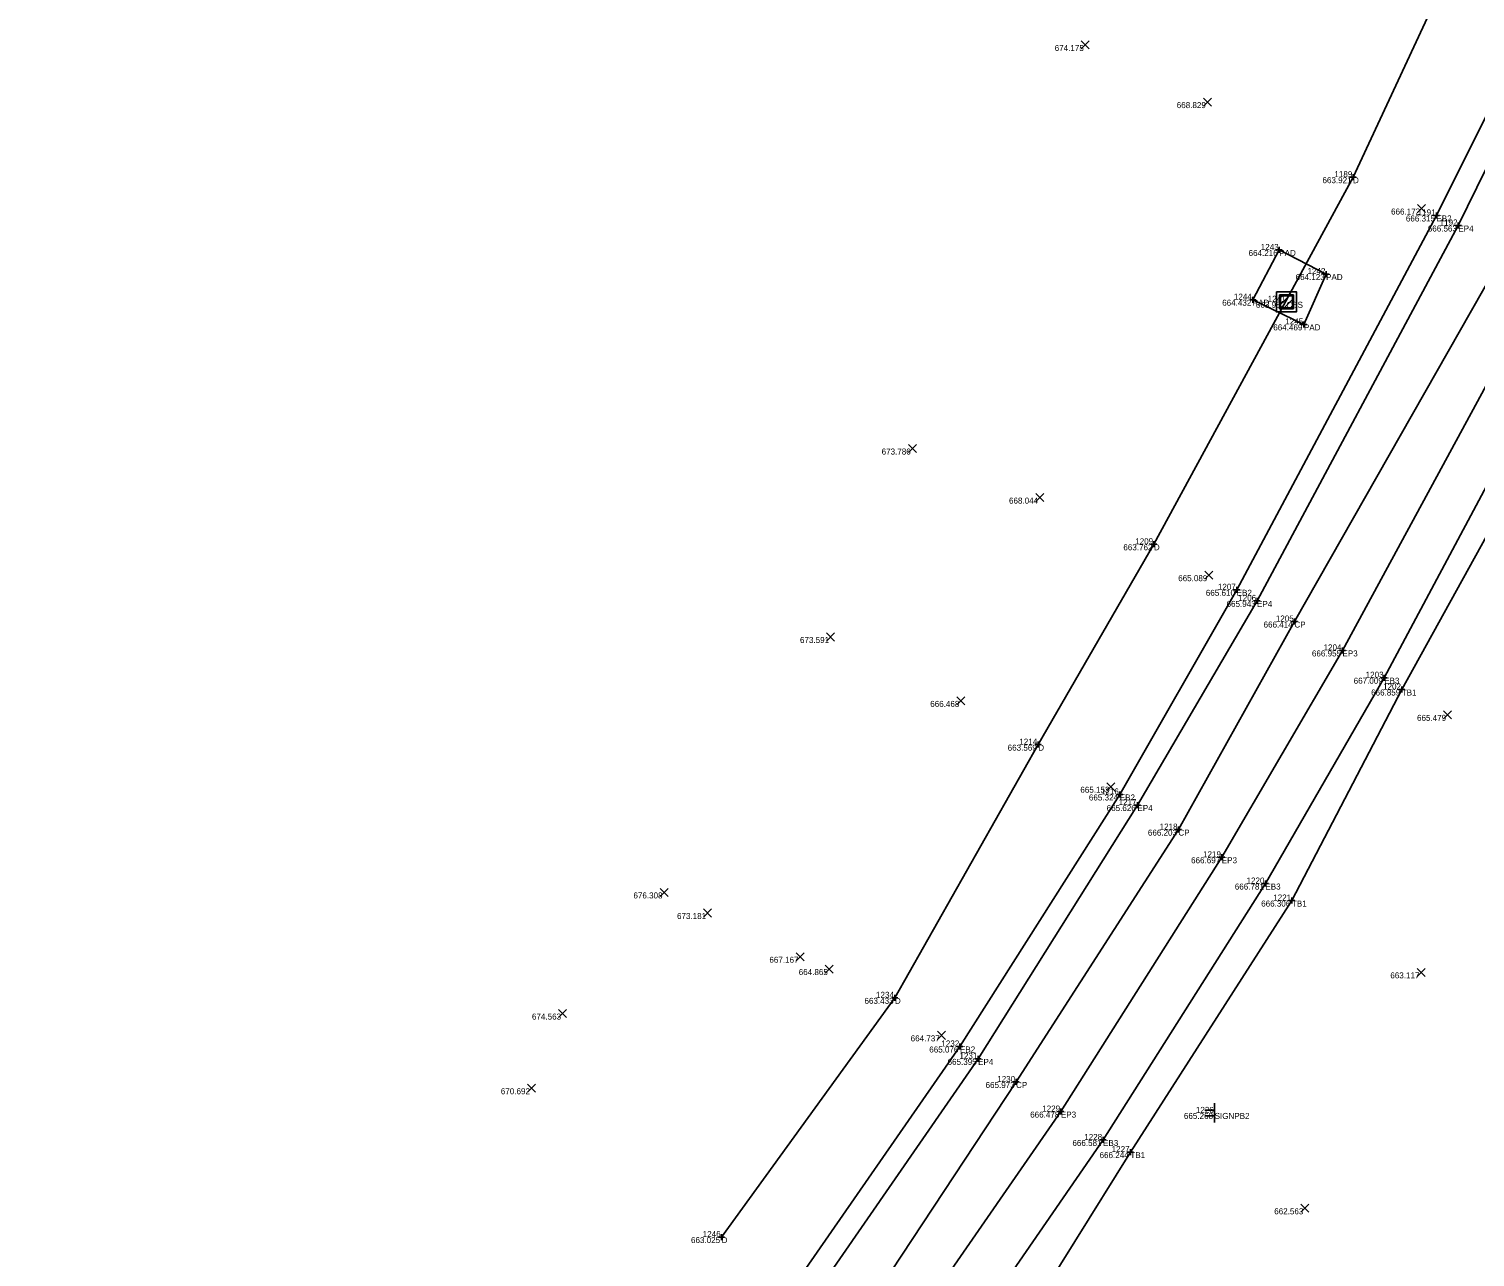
# Model space of a CAD drawing. Extents: x 2197382 to 2204062, y 634117 to 636522.
# Drawn here: x 2202848 to 2203088.2, y 635670.7 to 635874.6 of the extents above; entities that cross this region are included whole.
import ezdxf

# ---------------------------------------------------------------- set-up
doc = ezdxf.new("R2010")
doc.units = 0
for name, color, linetype in [('_CIVIL_CONSTRUCTION', 7, 'Continuous'), ('BR_P_Gen_Approach_Slab', 7, 'Continuous'), ('DR_X_Ditch', 7, 'Continuous'), ('GE_P_Alignment', 7, 'Continuous'), ('GE_P_Alignment_100_Cardinal_Points', 7, 'Continuous'), ('GE_P_Alignment_100_Distances', 7, 'Continuous'), ('GE_P_Alignment_100_Stations', 7, 'Continuous'), ('GE_X_Alignment', 7, 'Continuous'), ('PF_P_Grade_Line', 7, 'Continuous'), ('PV_X_COP', 7, 'Continuous'), ('RW_X_CL_100_Curve_Data', 7, 'Continuous'), ('SH_Border', 7, 'Continuous'), ('SH_Cut_Line', 7, 'Continuous'), ('SH_Data', 7, 'Continuous')]:
    doc.layers.add(name, color=color, linetype=linetype)

msp = doc.modelspace()

# ---------------------------------------------------------------- linework, layer by layer
at = {"layer": '_CIVIL_CONSTRUCTION'}
for p, q in [((2203067.39, 635850.01), (2203068.39, 635850.01)), ((2203067.89, 635850.51), (2203067.89, 635849.51)), ((2203067.89, 635850.01), (2203067.89, 635850.01)), ((2203081.23, 635843.65), (2203082.23, 635843.65)), ((2203081.73, 635844.15), (2203081.73, 635843.15)), ((2203081.73, 635843.65), (2203081.73, 635843.65)), ((2203084.87, 635841.98), (2203085.87, 635841.98)), ((2203085.37, 635842.48), (2203085.37, 635841.48)), ((2203085.37, 635841.98), (2203085.37, 635841.98)), ((2203055.14, 635837.92), (2203056.14, 635837.92)), ((2203055.64, 635838.42), (2203055.64, 635837.42)), ((2203055.64, 635837.92), (2203055.64, 635837.92)), ((2203062.91, 635833.92), (2203063.91, 635833.92)), ((2203063.41, 635834.42), (2203063.41, 635833.42)), ((2203063.41, 635833.92), (2203063.41, 635833.92)), ((2203050.73, 635829.66), (2203051.73, 635829.66)), ((2203051.23, 635830.16), (2203051.23, 635829.16)), ((2203051.23, 635829.66), (2203051.23, 635829.66)), ((2203059.73, 635826.06), (2203059.73, 635825.06)), ((2203059.23, 635825.56), (2203060.23, 635825.56)), ((2203059.73, 635825.56), (2203059.73, 635825.56)), ((2203034.31, 635789.04), (2203035.31, 635789.04)), ((2203034.81, 635789.54), (2203034.81, 635788.54)), ((2203034.81, 635789.04), (2203034.81, 635789.04)), ((2203048.06, 635781.48), (2203049.06, 635781.48)), ((2203048.56, 635781.98), (2203048.56, 635780.98)), ((2203048.56, 635781.48), (2203048.56, 635781.48)), ((2203051.94, 635780.14), (2203051.94, 635779.14)), ((2203051.44, 635779.64), (2203052.44, 635779.64)), ((2203051.94, 635779.64), (2203051.94, 635779.64)), ((2203057.65, 635776.21), (2203058.65, 635776.21)), ((2203058.15, 635776.71), (2203058.15, 635775.71)), ((2203058.15, 635776.21), (2203058.15, 635776.21)), ((2203065.63, 635771.41), (2203066.63, 635771.41)), ((2203066.13, 635771.91), (2203066.13, 635770.91)), ((2203066.13, 635771.41), (2203066.13, 635771.41)), ((2203072.57, 635766.88), (2203073.57, 635766.88)), ((2203073.07, 635767.38), (2203073.07, 635766.38)), ((2203073.07, 635766.88), (2203073.07, 635766.88)), ((2203075.48, 635764.92), (2203076.48, 635764.92)), ((2203075.98, 635765.42), (2203075.98, 635764.42)), ((2203075.98, 635764.92), (2203075.98, 635764.92)), ((2203015.61, 635756.26), (2203015.61, 635755.26)), ((2203015.11, 635755.76), (2203016.11, 635755.76)), ((2203015.61, 635755.76), (2203015.61, 635755.76)), ((2203028.65, 635747.49), (2203029.65, 635747.49)), ((2203029.15, 635747.99), (2203029.15, 635746.99)), ((2203029.15, 635747.49), (2203029.15, 635747.49)), ((2203031.58, 635745.73), (2203032.58, 635745.73)), ((2203032.08, 635746.23), (2203032.08, 635745.23)), ((2203032.08, 635745.73), (2203032.08, 635745.73)), ((2203038.88, 635742.15), (2203038.88, 635741.15)), ((2203038.38, 635741.65), (2203039.38, 635741.65)), ((2203038.88, 635741.65), (2203038.88, 635741.65)), ((2203045.59, 635737.06), (2203046.59, 635737.06)), ((2203046.09, 635737.56), (2203046.09, 635736.56)), ((2203046.09, 635737.06), (2203046.09, 635737.06)), ((2203052.83, 635732.69), (2203053.83, 635732.69)), ((2203053.33, 635733.19), (2203053.33, 635732.19)), ((2203053.33, 635732.69), (2203053.33, 635732.69)), ((2203057.24, 635729.87), (2203058.24, 635729.87)), ((2203057.74, 635730.37), (2203057.74, 635729.37)), ((2203057.74, 635729.87), (2203057.74, 635729.87)), ((2202991.31, 635713.71), (2202992.31, 635713.71)), ((2202991.81, 635714.21), (2202991.81, 635713.21)), ((2202991.81, 635713.71), (2202991.81, 635713.71)), ((2203002.11, 635705.63), (2203003.11, 635705.63)), ((2203002.61, 635706.13), (2203002.61, 635705.13)), ((2203002.61, 635705.63), (2203002.61, 635705.63)), ((2203005.12, 635703.58), (2203006.12, 635703.58)), ((2203005.62, 635704.08), (2203005.62, 635703.08)), ((2203005.62, 635703.58), (2203005.62, 635703.58)), ((2203011.42, 635699.74), (2203012.42, 635699.74)), ((2203011.92, 635700.24), (2203011.92, 635699.24)), ((2203011.92, 635699.74), (2203011.92, 635699.74)), ((2203018.87, 635694.82), (2203019.87, 635694.82)), ((2203019.37, 635695.32), (2203019.37, 635694.32)), ((2203019.37, 635694.82), (2203019.37, 635694.82)), ((2203025.87, 635690.11), (2203026.87, 635690.11)), ((2203026.37, 635690.61), (2203026.37, 635689.61)), ((2203026.37, 635690.11), (2203026.37, 635690.11)), ((2203030.41, 635688.09), (2203031.41, 635688.09)), ((2203030.91, 635688.59), (2203030.91, 635687.59)), ((2203030.91, 635688.09), (2203030.91, 635688.09)), ((2202963.02, 635674.48), (2202963.02, 635673.48)), ((2202962.52, 635673.98), (2202963.52, 635673.98)), ((2202963.02, 635673.98), (2202963.02, 635673.98))]:
    msp.add_line(p, q, dxfattribs=at)
at = {"layer": 'BR_P_Gen_Approach_Slab'}
msp.add_lwpolyline([(2203063.41, 635833.92), (2203055.64, 635837.92), (2203051.23, 635829.66), (2203059.73, 635825.56)], close=True, dxfattribs=at)
at = {"layer": 'DR_X_Ditch'}
msp.add_lwpolyline([(2203184.1, 636112.24), (2203164.63, 636065.3), (2203144.25, 636021.99), (2203126.27, 635973.65), (2203105.52, 635930.12), (2203083.98, 635884.54), (2203067.89, 635850.01), (2203034.81, 635789.04), (2203015.61, 635755.76), (2202991.81, 635713.71), (2202963.02, 635673.98)], dxfattribs=at)
at = {"layer": 'GE_P_Alignment'}
for p, q in [((2203055.68, 635828.69), (2203057.44, 635830.45)), ((2203055.68, 635829.83), (2203056.3, 635830.45)), ((2203056.28, 635828.16), (2203057.97, 635829.85)), ((2203057.41, 635828.16), (2203057.97, 635828.72))]:
    msp.add_line(p, q, dxfattribs=at)
for points in [[(2203055.16, 635830.97), (2203058.49, 635830.97), (2203058.49, 635827.64), (2203055.16, 635827.64)], [(2203055.68, 635830.45), (2203057.97, 635830.45), (2203057.97, 635828.16), (2203055.68, 635828.16)], [(2203055.82, 635830.31), (2203057.82, 635830.31), (2203057.82, 635828.31), (2203055.82, 635828.31)]]:
    msp.add_lwpolyline(points, close=True, dxfattribs=at)
at = {"layer": 'GE_P_Alignment_100_Cardinal_Points'}
for p, q in [((2203056.82, 635830.97), (2203056.82, 635830.97)), ((2203055.82, 635829.31), (2203055.82, 635829.31)), ((2203056.82, 635830.31), (2203056.82, 635830.31)), ((2203056.82, 635829.31), (2203056.82, 635829.31)), ((2203056.82, 635829.31), (2203056.82, 635829.31)), ((2203056.82, 635829.31), (2203056.82, 635829.31)), ((2203056.82, 635828.31), (2203056.82, 635828.31)), ((2203057.82, 635829.31), (2203057.82, 635829.31)), ((2203056.82, 635827.64), (2203056.82, 635827.64))]:
    msp.add_line(p, q, dxfattribs=at)
at = {"layer": 'GE_P_Alignment_100_Distances'}
for points in [[(2203324.48, 636507.85), (2203318.62, 636484.14), (2203306.91, 636435.63), (2203294.22, 636387.53), (2203281.02, 636340.01), (2203266.86, 636291.74), (2203251.88, 636244.73), (2203235.99, 636197.91), (2203219.31, 636150.6), (2203201.96, 636104.73), (2203183.73, 636058.36), (2203164.29, 636012.58), (2203144.31, 635966.64), (2203123.63, 635921.48), (2203102.28, 635876.46), (2203085.37, 635841.98), (2203051.94, 635779.64), (2203032.08, 635745.73), (2203005.62, 635703.58), (2202977.57, 635663.01), (2202948.44, 635623.54), (2202917.31, 635585.47), (2202885.13, 635547.53), (2202851.31, 635511.58)], [(2203340.49, 636502.89), (2203334.83, 636480.1), (2203323.13, 636431.59), (2203310.29, 636383.13), (2203297.23, 636335.04), (2203282.66, 636287.13), (2203267.38, 636239.56), (2203251.38, 636192.17), (2203234.81, 636145.08), (2203217.29, 636098.29), (2203199.14, 636051.74), (2203179.44, 636005.69), (2203159.56, 635959.77), (2203137.84, 635914.65), (2203117.45, 635869.06), (2203100.66, 635835.13), (2203066.13, 635771.41), (2203046.09, 635737.06), (2203019.37, 635694.82), (2202991.01, 635653.88), (2202961.19, 635613.48), (2202929.73, 635574.61), (2202897.41, 635536.46), (2202863.17, 635499.96)]]:
    msp.add_lwpolyline(points, dxfattribs=at)
at = {"layer": 'GE_P_Alignment_100_Stations'}
for p, q in [((2203044.9, 635696.2), (2203044.9, 635693)), ((2203044.9, 635695.08), (2203043.3, 635695.08)), ((2203044.9, 635694.12), (2203043.3, 635694.12)), ((2203044.9, 635694.6), (2203044.9, 635694.6))]:
    msp.add_line(p, q, dxfattribs=at)
at = {"layer": 'GE_X_Alignment'}
for points in [[(2203321.2, 636508.87), (2203315.42, 636484.99), (2203303.56, 636436.4), (2203290.91, 636388.48), (2203277.67, 636341.19), (2203263.29, 636292.83), (2203248.5, 636245.95), (2203232.65, 636199.01), (2203215.82, 636151.66), (2203198.58, 636105.93), (2203180.2, 636059.59), (2203161.3, 636014.11), (2203141.29, 635968.09), (2203120.26, 635923.09), (2203098.92, 635878.1), (2203081.73, 635843.65), (2203048.56, 635781.48), (2203029.15, 635747.49), (2203002.61, 635705.63), (2202974.64, 635665.31), (2202945.56, 635625.56), (2202914.38, 635588.2), (2202882.41, 635550.01), (2202847.99, 635514.11)], [(2203331.27, 636429.38), (2203318.29, 636380.99), (2203304.79, 636332.88), (2203290.18, 636284.77), (2203275.23, 636236.57), (2203259.29, 636189.41), (2203242.5, 636142.16), (2203224.73, 636095.35), (2203206.44, 636048.57), (2203187.1, 636002.46), (2203167.05, 635956.43), (2203145.71, 635910.9), (2203124.58, 635865.62), (2203107.54, 635831.47), (2203073.07, 635766.88), (2203053.33, 635732.69), (2203026.37, 635690.11), (2202997.51, 635648.24), (2202967.93, 635608.32), (2202935.99, 635569.18), (2202902.86, 635531.15), (2202868.61, 635494.33)]]:
    msp.add_lwpolyline(points, dxfattribs=at)
at = {"layer": 'PF_P_Grade_Line'}
msp.add_lwpolyline([(2203263.6, 636187.64), (2203248.97, 636139.91), (2203228.73, 636093.53), (2203209.69, 636047.17), (2203190.81, 636000.71), (2203171.68, 635954.63), (2203151.19, 635908.23), (2203127.58, 635864.5), (2203111.43, 635829.11), (2203075.98, 635764.92), (2203057.74, 635729.87), (2203030.91, 635688.09), (2203003.19, 635643.55), (2202971.04, 635606.63), (2202940.16, 635565.41)], dxfattribs=at)
at = {"layer": 'PV_X_COP'}
msp.add_lwpolyline([(2203333.12, 636504.55), (2203327.23, 636481.85), (2203314.64, 636433.62), (2203302.94, 636385.15), (2203289.25, 636336.51), (2203274.73, 636289.23), (2203259.31, 636242.63), (2203243.41, 636195.32), (2203226.43, 636148.15), (2203210.06, 636101.18), (2203190.93, 636055.28), (2203172.74, 636008.76), (2203151.47, 635963.31), (2203132.08, 635917.44), (2203109.53, 635872.8), (2203093.5, 635838.3), (2203058.15, 635776.21), (2203038.88, 635741.65), (2203011.92, 635699.74), (2202984.39, 635657.94), (2202954.68, 635618.56), (2202923.73, 635579.74), (2202891.73, 635541.49), (2202857.33, 635505.37)], dxfattribs=at)
at = {"layer": 'RW_X_CL_100_Curve_Data'}
for p, q in [((2203022.74, 635871.3), (2203024.08, 635872.63)), ((2203022.74, 635872.63), (2203024.08, 635871.3)), ((2203043.03, 635861.81), (2203044.36, 635863.15)), ((2203043.03, 635863.15), (2203044.36, 635861.81)), ((2203078.6, 635844.13), (2203079.94, 635845.46)), ((2203078.6, 635845.46), (2203079.94, 635844.13)), ((2202994.04, 635804.27), (2202995.37, 635805.61)), ((2202994.04, 635805.61), (2202995.37, 635804.27)), ((2203015.21, 635796.12), (2203016.54, 635797.45)), ((2203015.21, 635797.45), (2203016.54, 635796.12)), ((2203043.26, 635783.24), (2203044.6, 635784.58)), ((2203043.26, 635784.58), (2203044.6, 635783.24)), ((2202980.46, 635772.97), (2202981.79, 635774.31)), ((2202980.46, 635774.31), (2202981.79, 635772.97)), ((2203002.1, 635762.36), (2203003.43, 635763.7)), ((2203002.1, 635763.7), (2203003.43, 635762.36)), ((2203082.93, 635760.04), (2203084.26, 635761.38)), ((2203082.93, 635761.38), (2203084.26, 635760.04)), ((2203027, 635748.1), (2203028.33, 635749.44)), ((2203027, 635749.44), (2203028.33, 635748.1)), ((2202952.81, 635730.55), (2202954.15, 635731.89)), ((2202952.81, 635731.89), (2202954.15, 635730.55)), ((2202960.04, 635727.13), (2202961.37, 635728.47)), ((2202960.04, 635728.47), (2202961.37, 635727.13)), ((2202975.38, 635719.86), (2202976.72, 635721.2)), ((2202975.38, 635721.2), (2202976.72, 635719.86)), ((2202980.24, 635717.83), (2202981.57, 635719.16)), ((2202980.24, 635719.16), (2202981.57, 635717.83)), ((2203078.51, 635717.27), (2203079.84, 635718.6)), ((2203078.51, 635718.6), (2203079.84, 635717.27)), ((2202935.93, 635710.43), (2202937.26, 635711.77)), ((2202935.93, 635711.77), (2202937.26, 635710.43)), ((2202998.85, 635706.81), (2203000.19, 635708.15)), ((2202998.85, 635708.15), (2203000.19, 635706.81)), ((2202930.77, 635698.03), (2202932.1, 635699.36)), ((2202930.77, 635699.36), (2202932.1, 635698.03)), ((2203059.19, 635678.1), (2203060.53, 635679.43)), ((2203059.19, 635679.43), (2203060.53, 635678.1))]:
    msp.add_line(p, q, dxfattribs=at)

# ---------------------------------------------------------------- texts
at = {"layer": 'SH_Border'}
for s, p in [('D', (2203067.89, 635849.01)), ('EB2', (2203081.73, 635842.65)), ('EP4', (2203085.37, 635840.98)), ('PAD', (2203055.64, 635836.92)), ('PAD', (2203063.41, 635832.92)), ('PAD', (2203051.23, 635828.66)), ('CBS', (2203056.82, 635828.31)), ('PAD', (2203059.73, 635824.56)), ('D', (2203034.81, 635788.04)), ('EB2', (2203048.56, 635780.48)), ('EP4', (2203051.94, 635778.64)), ('CP', (2203058.15, 635775.21)), ('EP3', (2203066.13, 635770.41)), ('EB3', (2203073.07, 635765.88)), ('TB1', (2203075.98, 635763.92)), ('D', (2203015.61, 635754.76)), ('EB2', (2203029.15, 635746.49)), ('EP4', (2203032.08, 635744.73)), ('CP', (2203038.88, 635740.65)), ('EP3', (2203046.09, 635736.06)), ('EB3', (2203053.33, 635731.69)), ('TB1', (2203057.74, 635728.87)), ('D', (2202991.81, 635712.71)), ('EB2', (2203002.61, 635704.63)), ('EP4', (2203005.62, 635702.58)), ('CP', (2203011.92, 635698.74)), ('EP3', (2203019.37, 635693.82)), ('SIGNPB2', (2203044.9, 635693.6)), ('EB3', (2203026.37, 635689.11)), ('TB1', (2203030.91, 635687.09)), ('D', (2202963.02, 635672.98))]:
    msp.add_text(s, height=1, dxfattribs=at).set_placement(p)
at = {"layer": 'SH_Cut_Line'}
for s, p in [('1189', (2203064.79, 635850.01)), ('1191', (2203078.63, 635843.65)), ('1192', (2203082.27, 635841.98)), ('1243', (2203052.56, 635837.92)), ('1242', (2203060.32, 635833.92)), ('1244', (2203048.09, 635829.66)), ('1241', (2203053.72, 635829.31)), ('1245', (2203056.64, 635825.56)), ('1209', (2203031.71, 635789.04)), ('1207', (2203045.44, 635781.48)), ('1206', (2203048.82, 635779.64)), ('1205', (2203055.06, 635776.21)), ('1204', (2203062.99, 635771.41)), ('1203', (2203069.99, 635766.88)), ('1202', (2203072.88, 635764.92)), ('1214', (2203012.47, 635755.76)), ('1216', (2203026.02, 635747.49)), ('1217', (2203028.96, 635745.73)), ('1218', (2203035.77, 635741.65)), ('1219', (2203042.98, 635737.06)), ('1220', (2203050.2, 635732.69)), ('1221', (2203054.64, 635729.87)), ('1234', (2202988.67, 635713.71)), ('1232', (2202999.52, 635705.63)), ('1231', (2203002.52, 635703.58)), ('1230', (2203008.79, 635699.74)), ('1229', (2203016.27, 635694.82)), ('1226', (2203041.78, 635694.6)), ('1228', (2203023.25, 635690.11)), ('1227', (2203027.8, 635688.09)), ('1246', (2202959.89, 635673.98))]:
    msp.add_text(s, height=1, dxfattribs=at).set_placement(p)
at = {"layer": 'SH_Data'}
for s, p in [('674.175', (2203018.34, 635870.96)), ('668.829', (2203038.61, 635861.48)), ('663.921', (2203062.81, 635849.01)), ('666.172', (2203074.2, 635843.8)), ('666.315', (2203076.66, 635842.65)), ('666.563', (2203080.3, 635840.98)), ('664.216', (2203050.54, 635836.92)), ('664.123', (2203058.35, 635832.92)), ('664.432', (2203046.16, 635828.66)), ('663.982', (2203051.75, 635828.31)), ('664.469', (2203054.64, 635824.56)), ('673.786', (2202989.6, 635803.94)), ('668.044', (2203010.75, 635795.79)), ('663.762', (2203029.74, 635788.04)), ('665.089', (2203038.85, 635782.91)), ('665.610', (2203043.44, 635780.48)), ('665.943', (2203046.88, 635778.64)), ('666.414', (2203053.03, 635775.21)), ('673.591', (2202976.04, 635772.64)), ('666.955', (2203061.06, 635770.41)), ('667.009', (2203067.99, 635765.88)), ('666.859', (2203070.89, 635763.92)), ('666.468', (2202997.67, 635762.03)), ('665.479', (2203078.51, 635759.71)), ('663.569', (2203010.53, 635754.76)), ('665.153', (2203022.6, 635747.77)), ('665.324', (2203024.02, 635746.49)), ('665.626', (2203026.97, 635744.73)), ('666.203', (2203033.82, 635740.65)), ('666.697', (2203040.99, 635736.06)), ('666.781', (2203048.25, 635731.69)), ('676.308', (2202948.38, 635730.22)), ('666.306', (2203052.63, 635728.87)), ('673.181', (2202955.62, 635726.8)), ('667.167', (2202970.96, 635719.53)), ('664.865', (2202975.83, 635717.49)), ('663.117', (2203074.08, 635716.94)), ('663.433', (2202986.75, 635712.71)), ('674.563', (2202931.53, 635710.1)), ('664.737', (2202994.42, 635706.48)), ('665.076', (2202997.51, 635704.63)), ('665.395', (2203000.55, 635702.58)), ('670.692', (2202926.36, 635697.7)), ('665.973', (2203006.86, 635698.74)), ('666.478', (2203014.27, 635693.82)), ('665.268', (2203039.8, 635693.6)), ('666.581', (2203021.28, 635689.11)), ('666.244', (2203025.79, 635687.09)), ('662.563', (2203054.8, 635677.76)), ('663.025', (2202957.94, 635672.98))]:
    msp.add_text(s, height=1, dxfattribs=at).set_placement(p)

doc.saveas('drawing.dxf')
